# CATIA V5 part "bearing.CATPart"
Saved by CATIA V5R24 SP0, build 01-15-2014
Part number: bearing
Bounding box of the stored display mesh (mm): x -8 to 8, y -20 to 20, z -20 to 20
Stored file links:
  G:\내 드라이브\04_WORK\00_LECTURE\CAD2020\exam\bearing.CATPart
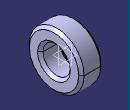
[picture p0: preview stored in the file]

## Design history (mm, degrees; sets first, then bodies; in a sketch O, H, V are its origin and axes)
Body1 (main body)
  Sketch1 on yz-plane, origin (0, 0, 0), H (0, 1, 0), V (0, 0, 1)
    circle A1 centre (0, 0) radius 10
    circle A2 centre (0, 0) radius 20
    radius A1 = 10
    radius A2 = 20
  Pad1: profile Sketch1, direction (1, 0, 0), length 8, mirrored extent
  Chamfer1: length 2, angle 45, on face of Pad1 from Sketch1.A1; face of Pad1 from Sketch1.A2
